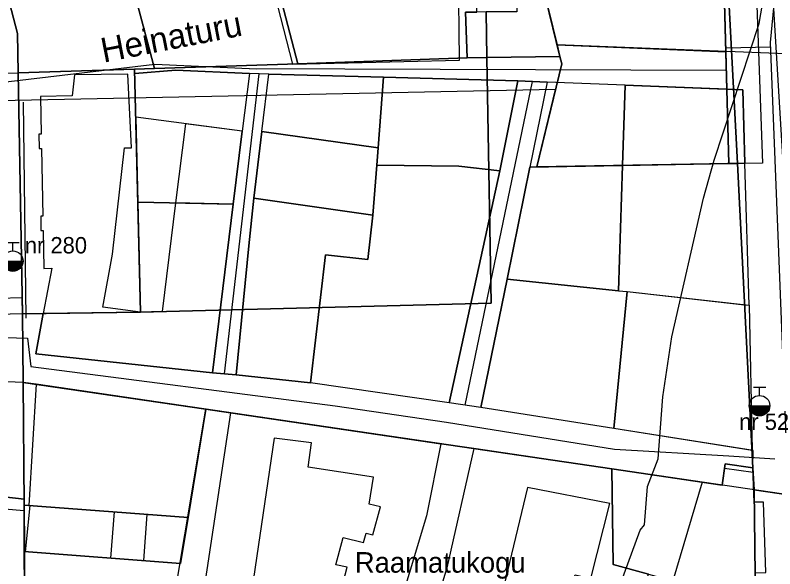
# Model space of a CAD drawing. Extents: x 728832 to 739469, y 6586263 to 6599699.
# Drawn here: x 738581.2 to 738766.3, y 6589820.2 to 6589955.2 of the extents above; entities that cross this region are included whole.
import ezdxf

# ---------------------------------------------------------------- set-up
doc = ezdxf.new("R2010")
doc.units = 0
for name, color, linetype in [('a_kalda_piiranguv', 7, 'Continuous'), ('a_LK_III_kodukakk', 7, 'Continuous'), ('a_piir', 7, 'Continuous'), ('dp_hoonestus', 7, 'Continuous'), ('PIIR', 7, 'Continuous'), ('plan_ala', 7, 'Continuous'), ('v_dp_kaldapromenaad', 7, 'Continuous'), ('v_dp_kehtiv', 7, 'Continuous'), ('v_dp_kehtiv_tekst', 7, 'Continuous'), ('v_dp_tanav_tekst', 7, 'Continuous'), ('v_dp_transp_kergliiklejate_tanav', 7, 'Continuous'), ('v_leppem_katastripiir', 7, 'Continuous'), ('v_olol_hüdrant', 7, 'Continuous'), ('v_olol_katastri_nimi', 7, 'Continuous'), ('v_olol_transp_jjt', 7, 'Continuous'), ('VKAEV', 7, 'Continuous')]:
    doc.layers.add(name, color=color, linetype=linetype)

# ---------------------------------------------------------------- blocks, each defined once
blk = doc.blocks.new('THYDRM_3')
at = {"layer": 'VKAEV'}
for p, q in [((-0.6, 1.8), (0.6, 1.8)), ((0, 1), (0, 1.8)), ((-1, 0), (1, 0))]:
    blk.add_line(p, q, dxfattribs=at)
blk.add_circle((0, 0), 1, dxfattribs=at)
for radius in [0.95, 0.9, 0.85, 0.8, 0.75, 0.7, 0.65, 0.6, 0.55, 0.5, 0.45, 0.4, 0.35, 0.3, 0.25, 0.2, 0.15, 0.1]:
    blk.add_arc((0, 0), radius, 180, 0, dxfattribs=at)

msp = doc.modelspace()

# ---------------------------------------------------------------- linework, layer by layer
at = {"layer": 'a_kalda_piiranguv'}
msp.add_lwpolyline([(738695.61, 6589728.48), (738706.15, 6589759.08), (738722.64, 6589798.76), (738722.69, 6589800.12), (738733.47, 6589829.62), (738734.51, 6589830.94), (738735.22, 6589840.26), (738737.86, 6589847.06), (738738.99, 6589862.11), (738741.2, 6589876.8), (738748.87, 6589910.57), (738751.45, 6589919.82), (738762.48, 6589953.16), (738771.98, 6590008.5), (738779.42, 6590032.77), (738792.73, 6590054.38), (738794.61, 6590056.71), (738798, 6590073.89), (738805.74, 6590098.09)], dxfattribs=at)
at = {"layer": 'a_LK_III_kodukakk'}
msp.add_lwpolyline([(738774.8, 6589988.29), (738764.14, 6589986.28), (738769.19, 6589903.2), (738776.34, 6589779.97), (738793.46, 6589779), (738813.32, 6589799.46), (738821.04, 6589844.98), (738829.66, 6589892.22), (738832, 6589940.61), (738821.77, 6589948.75), (738824.98, 6589976.65)], close=True, dxfattribs=at)
at = {"layer": 'a_piir'}
for points in [[(738716.96, 6590090.08), (738738.99, 6590049.61), (738748.53, 6590037.67), (738752.27, 6590014.17), (738752.88, 6590000.39), (738757.06, 6589920.61), (738757.14, 6589919.04), (738760.94, 6589844.8), (738761.22, 6589839.49), (738773.4, 6589837.7), (738772.93, 6589857.45), (738768.72, 6589952.16), (738772.03, 6590000.09), (738764.49, 6590055.06), (738742.13, 6590093.07)], [(738746.35, 6589684.41), (738770.95, 6589773.79), (738773.02, 6589782.57), (738774.3, 6589799.69), (738773.4, 6589837.7), (738761.22, 6589839.49), (738761.57, 6589811.73), (738761.83, 6589791.03), (738753.47, 6589756.53), (738744.47, 6589720.57)]]:
    msp.add_lwpolyline(points, dxfattribs=at)
for points in [[(738689.52, 6590022.24), (738633.27, 6590007.58), (738650.05, 6589943.32), (738691.26, 6589944.8), (738690.88, 6589955.96), (738693.65, 6589955.95), (738693.65, 6589965.82), (738703.46, 6589965.87), (738703.41, 6589956.03), (738695.91, 6589955.97), (738696.09, 6589944.86), (738713.89, 6589945.13), (738703.51, 6589987.79), (738698.18, 6589986.41)], [(738615.11, 6589942.17), (738650.05, 6589943.32), (738633.27, 6590007.58), (738600.07, 6589998.83)], [(738752.88, 6590000.39), (738703.51, 6589987.79), (738713.89, 6589945.13), (738714.33, 6589943.33), (738708.27, 6589918.18), (738755.04, 6589919)], [(738757.06, 6589920.61), (738752.88, 6590000.39), (738755.04, 6589919), (738757.14, 6589919.04)], [(738615.11, 6589942.17), (738600.07, 6589998.83), (738571.13, 6589991.27), (738581.73, 6589950.74), (738581.9, 6589941.15), (738610.26, 6589942.03)], [(738571.13, 6589991.27), (738553.84, 6589986.61), (738562.2, 6589955.79), (738564.38, 6589947.59), (738565.01, 6589911.26), (738565.45, 6589885.78), (738577.13, 6589865.85), (738573.7, 6589835.23), (738572.34, 6589823.37), (738572.85, 6589780.14), (738565.96, 6589779.81), (738566.36, 6589741.08), (738583.93, 6589742.58), (738583.56, 6589797.78), (738583.38, 6589824.42), (738583.34, 6589835.74), (738583.11, 6589865.67), (738582.94, 6589882.38), (738581.9, 6589941.15), (738581.73, 6589950.74)], [(738696.09, 6589944.86), (738695.91, 6589955.97), (738693.65, 6589955.95), (738690.88, 6589955.96), (738691.26, 6589944.8)], [(738696.09, 6589944.86), (738697.14, 6589884.98), (738611.71, 6589882.8), (738582.94, 6589882.38), (738583.11, 6589865.67), (738627.65, 6589859.12), (738726.53, 6589844.6), (738753.42, 6589840.65), (738754.18, 6589845.8), (738760.94, 6589844.8), (738757.14, 6589919.04), (738755.04, 6589919), (738708.27, 6589918.18), (738714.33, 6589943.33), (738713.89, 6589945.13)], [(738650.05, 6589943.32), (738615.11, 6589942.17), (738610.26, 6589942.03), (738611.71, 6589882.8), (738697.14, 6589884.98), (738696.09, 6589944.86), (738691.26, 6589944.8)], [(738581.9, 6589941.15), (738582.94, 6589882.38), (738611.71, 6589882.8), (738610.26, 6589942.03)], [(738627.65, 6589859.12), (738583.11, 6589865.67), (738583.34, 6589835.74), (738623.29, 6589832.73)], [(738623.29, 6589832.73), (738621.44, 6589821.55), (738583.38, 6589824.42), (738583.56, 6589797.78), (738610.5, 6589797.85), (738634.41, 6589797.92), (738645.6, 6589795.94), (738680.72, 6589789.71), (738724.38, 6589781.99), (738735.47, 6589818.89), (738726.85, 6589821.26), (738726.53, 6589844.6), (738627.65, 6589859.12)], [(738726.53, 6589844.6), (738726.85, 6589821.26), (738735.47, 6589818.89), (738761.57, 6589811.73), (738761.22, 6589839.49), (738760.94, 6589844.8), (738754.18, 6589845.8), (738753.42, 6589840.65)], [(738583.38, 6589824.42), (738621.44, 6589821.55), (738623.29, 6589832.73), (738583.34, 6589835.74)]]:
    msp.add_lwpolyline(points, close=True, dxfattribs=at)
at = {"layer": 'dp_hoonestus'}
msp.add_line((738607.77, 6589922.88), (738609.51, 6589922.85), dxfattribs=at)
for points in [[(738609.51, 6589922.85), (738608.58, 6589940.82), (738595.65, 6589940.61), (738595.08, 6589935.52), (738587.34, 6589935.36), (738587.51, 6589926.18), (738586.91, 6589926.17), (738586.97, 6589922.7), (738587.58, 6589922.71), (738587.9, 6589906.2), (738587.38, 6589906.19), (738587.44, 6589902.71), (738587.97, 6589902.72), (738588.15, 6589893.45), (738590.07, 6589893.5), (738588.02, 6589882.45), (738611.71, 6589882.8), (738602.54, 6589883.97), (738604.89, 6589896.91), (738607.77, 6589922.88)], [(738629.28, 6589868.02), (738634.32, 6589909.08), (738636.51, 6589926.89)]]:
    msp.add_lwpolyline(points, dxfattribs=at)
for points in [[(738638.24, 6589940.95), (738636.51, 6589926.89), (738610.55, 6589930.29), (738610.29, 6589940.96), (738620.34, 6589941.8), (738638.24, 6589940.95)], [(738641.25, 6589926.82), (738642.96, 6589940.78), (738670.91, 6589940.04), (738669.59, 6589922.84), (738641.25, 6589926.82)], [(738669.27, 6589918.64), (738669.59, 6589922.84), (738670.91, 6589940.04), (738703.67, 6589939.18), (738699.26, 6589917.24), (738689.3, 6589918.41), (738669.27, 6589918.64)], [(738710.82, 6589938.87), (738706.6, 6589918.15), (738729.15, 6589918.55), (738729.77, 6589938.09), (738710.82, 6589938.87)], [(738729.15, 6589918.55), (738729.77, 6589938.09), (738758.48, 6589936.98), (738758.99, 6589919.07), (738755.04, 6589919), (738729.15, 6589918.55)], [(738622.63, 6589928.71), (738620.26, 6589909.4), (738634.32, 6589909.08), (738636.51, 6589926.89), (738622.63, 6589928.71)], [(738639.28, 6589910.55), (738641.25, 6589926.82), (738669.59, 6589922.84), (738669.27, 6589918.64), (738668.33, 6589906.41), (738639.28, 6589910.55)], [(738653.16, 6589865.56), (738656.76, 6589896.8), (738667.09, 6589895.61), (738668.33, 6589906.41), (738669.27, 6589918.64), (738689.3, 6589918.41), (738699.26, 6589917.24), (738686.91, 6589860.69), (738653.16, 6589865.56)], [(738706.6, 6589918.15), (738729.15, 6589918.55), (738728.17, 6589888.01), (738701.03, 6589890.82), (738706.6, 6589918.15)], [(738729.15, 6589918.55), (738728.17, 6589888.01), (738730.27, 6589887.79), (738759.98, 6589884.48), (738758.99, 6589919.07), (738729.15, 6589918.55)], [(738620.26, 6589909.4), (738617.01, 6589882.94), (738611.71, 6589882.8), (738588.02, 6589882.45), (738586.18, 6589872.62), (738615.36, 6589869.51), (738629.28, 6589868.02), (738634.32, 6589909.08), (738620.26, 6589909.4)], [(738635, 6589867.5), (738638.13, 6589898.93), (738639.28, 6589910.55), (738668.33, 6589906.41), (738667.09, 6589895.61), (738656.76, 6589896.8), (738653.16, 6589865.56), (738635, 6589867.5)], [(738694.66, 6589859.54), (738701.03, 6589890.82), (738728.17, 6589888.01), (738730.27, 6589887.79), (738727.07, 6589854.42), (738694.66, 6589859.54)], [(738730.27, 6589887.79), (738759.98, 6589884.48), (738760.72, 6589849.1), (738727.07, 6589854.42), (738730.27, 6589887.79)]]:
    msp.add_lwpolyline(points, close=True, dxfattribs=at)
at = {"layer": 'PIIR'}
for points in [[(738638.81, 6589815.08), (738640.53, 6589814.8), (738657.11, 6589810.8), (738657.17, 6589811.05), (738663.17, 6589809.58), (738664.84, 6589815.82), (738661.09, 6589816.92), (738662.08, 6589820.59), (738659.31, 6589821.21), (738661.1, 6589827.82), (738666.07, 6589826.65), (738666.65, 6589828.92), (738668.33, 6589828.52), (738670.17, 6589835.36), (738667.45, 6589835.99), (738668.47, 6589842.54), (738652.59, 6589845), (738653.37, 6589850.95), (738644.27, 6589852.09)], [(738741.43, 6589817.25), (738761.57, 6589811.73), (738761.48, 6589819.2), (738764.07, 6589819.32), (738763.48, 6589836.46), (738761.26, 6589836.45), (738761.22, 6589839.49), (738761, 6589843.69), (738754.02, 6589844.71), (738753.42, 6589840.65), (738748.6, 6589841.36)], [(738696.35, 6589799.74), (738708.31, 6589795.99), (738710.1, 6589802.4), (738718.62, 6589799.79), (738721.96, 6589811.57), (738716.18, 6589813.25), (738717.59, 6589818.79), (738721.47, 6589817.83), (738726.05, 6589836.16), (738706, 6589840.01)], [(738605.27, 6589834.09), (738604.43, 6589822.83), (738583.7, 6589824.4), (738584.85, 6589835.63)], [(738613.23, 6589833.49), (738612.4, 6589822.23), (738621.44, 6589821.55), (738623.29, 6589832.73)]]:
    msp.add_lwpolyline(points, close=True, dxfattribs=at)
at = {"layer": 'plan_ala'}
msp.add_lwpolyline([(738773.4, 6589837.7), (738586.3, 6589865.2), (738586.3, 6589865.2), (738583.11, 6589865.67), (738577.13, 6589865.85), (738565.7, 6589866.14), (738565.45, 6589885.77), (738564.49, 6589941.05), (738581.9, 6589941.15), (738615.11, 6589942.17), (738650.05, 6589943.32), (738691.27, 6589944.8), (738696.09, 6589944.85), (738713.89, 6589945.13), (738703.51, 6589987.79), (738786.92, 6590008.4), (738768.72, 6589952.16)], close=True, dxfattribs=at)
at = {"layer": 'v_dp_kaldapromenaad'}
for p, q in [((738632.14, 6589867.76), (738640.6, 6589940.86)), ((738754.44, 6589941.71), (738638.3, 6589942.12)), ((738690.79, 6589860.12), (738707.24, 6589939.02))]:
    msp.add_line(p, q, dxfattribs=at)
at = {"layer": 'v_dp_kehtiv'}
for points in [[(738572.16, 6589949.69), (738560.05, 6589994.65), (738754.16, 6590045.25), (738754.16, 6590045.25), (738759.38, 6590027.73), (738763.29, 6589919.13), (738757.14, 6589919.04), (738708.27, 6589918.18), (738712.82, 6589937.07), (738573.1, 6589934.21)], [(738560.05, 6589994.65), (738754.16, 6590045.25), (738754.16, 6590045.25), (738759.38, 6590027.73), (738763.29, 6589919.13), (738757.14, 6589919.04), (738708.27, 6589918.18), (738712.82, 6589937.07), (738573.1, 6589934.21), (738572.16, 6589949.69)], [(738689.18, 6589965.94), (738689.18, 6589965.94), (738708.83, 6589965.94), (738703.51, 6589987.79), (738753.01, 6590000.42), (738754.21, 6590000.8), (738753.82, 6590014.6), (738749.4, 6590039.21), (738749.4, 6590039.21), (738631.94, 6590008.72), (738631.94, 6590008.72), (738648.75, 6589943.28), (738648.75, 6589943.28), (738648.75, 6589943.28), (738689.41, 6589944.25), (738689.41, 6589944.25)], [(738689.18, 6589965.94), (738689.18, 6589965.94), (738708.83, 6589965.94), (738703.51, 6589987.79), (738753.01, 6590000.42), (738754.21, 6590000.8), (738753.82, 6590014.6), (738749.4, 6590039.21), (738749.4, 6590039.21), (738631.94, 6590008.72), (738631.94, 6590008.72), (738648.75, 6589943.28), (738648.75, 6589943.28), (738648.75, 6589943.28), (738689.41, 6589944.25), (738689.41, 6589944.25)], [(738696.09, 6589944.85), (738697.14, 6589884.98), (738611.71, 6589882.8), (738582.94, 6589882.38), (738570.92, 6589882.05), (738572.64, 6589797.79), (738583.56, 6589797.78), (738610.5, 6589797.85), (738634.41, 6589797.92), (738645.6, 6589795.94), (738724.38, 6589781.99), (738735.47, 6589818.89), (738761.57, 6589811.73), (738774.1, 6589808.27), (738773.4, 6589837.7), (738768.98, 6589945.74), (738713.21, 6589947.93), (738713.89, 6589945.13)], [(738696.09, 6589944.85), (738697.14, 6589884.98), (738611.71, 6589882.8), (738582.94, 6589882.38), (738570.92, 6589882.05), (738572.64, 6589797.79), (738583.56, 6589797.78), (738610.5, 6589797.85), (738634.41, 6589797.92), (738645.6, 6589795.94), (738724.38, 6589781.99), (738735.47, 6589818.89), (738761.57, 6589811.73), (738774.1, 6589808.27), (738773.4, 6589837.7), (738768.98, 6589945.74), (738713.21, 6589947.93), (738713.89, 6589945.13)], [(738583.69, 6589778.96), (738583.56, 6589797.78), (738583.33, 6589837.2), (738518.88, 6589844.63), (738518.26, 6589795.24), (738518.24, 6589794.66), (738518.47, 6589777.9), (738518.47, 6589777.9), (738583.69, 6589778.96), (738583.69, 6589778.96), (738583.69, 6589778.96)], [(738518.88, 6589844.63), (738518.88, 6589844.63), (738518.88, 6589844.63), (738518.88, 6589844.63), (738583.33, 6589837.2), (738583.33, 6589837.2), (738583.56, 6589797.78), (738583.69, 6589778.96), (738583.69, 6589778.96), (738583.69, 6589778.96), (738518.49, 6589777.9), (738518.47, 6589777.9), (738518.24, 6589794.66), (738518.26, 6589795.24)]]:
    msp.add_lwpolyline(points, close=True, dxfattribs=at)
for points in [[(738573.7, 6589835.23), (738583.34, 6589834.45), (738583.34, 6589835.74), (738583.11, 6589865.67), (738582.94, 6589882.36), (738582.87, 6589886.28), (738565.45, 6589885.77)], [(738573.7, 6589835.23), (738583.34, 6589834.45), (738583.34, 6589835.74), (738583.11, 6589865.67), (738582.94, 6589882.38), (738582.87, 6589886.28), (738565.45, 6589885.77)]]:
    msp.add_lwpolyline(points, dxfattribs=at)
at = {"layer": 'v_dp_transp_kergliiklejate_tanav'}
for p, q in [((738754.29, 6589947.22), (738765.2, 6589947.47)), ((738583.87, 6589881.32), (738583.17, 6589934.01))]:
    msp.add_line(p, q, dxfattribs=at)
for points in [[(738566.56, 6589937.49), (738615.22, 6589943.27), (738639.96, 6589942.08)], [(738568.16, 6589876.93), (738584.15, 6589876.47), (738585, 6589869.54), (738659.13, 6589859.93), (738686.28, 6589855.99), (738727.22, 6589849.37), (738755.03, 6589847.73), (738766.25, 6589847.05)]]:
    msp.add_lwpolyline(points, dxfattribs=at)
at = {"layer": 'v_leppem_katastripiir'}
for p, q in [((738586.3, 6589865.2), (738627.65, 6589859.12)), ((738633.66, 6589858.24), (738684.92, 6589850.71)), ((738748.6, 6589841.36), (738741.43, 6589817.25)), ((738584.46, 6589835.66), (738623.29, 6589832.73)), ((738583.38, 6589824.42), (738621.44, 6589821.55))]:
    msp.add_line(p, q, dxfattribs=at)
for points in [[(738584.46, 6589835.66), (738583.34, 6589835.74), (738583.11, 6589865.67), (738586.3, 6589865.2)], [(738617.39, 6589797.87), (738627.65, 6589859.12), (738633.66, 6589858.24), (738624.54, 6589797.89)]]:
    msp.add_lwpolyline(points, close=True, dxfattribs=at)
for points in [[(738624.54, 6589797.89), (738634.41, 6589797.92), (738645.6, 6589795.94), (738668.95, 6589791.8), (738680.72, 6589789.71), (738724.38, 6589781.99), (738735.47, 6589818.89), (738761.57, 6589811.73), (738761.48, 6589819.2), (738764.07, 6589819.32), (738763.48, 6589836.46), (738761.26, 6589836.45), (738760.94, 6589844.8), (738754.18, 6589845.8), (738753.42, 6589840.65), (738692.91, 6589849.54), (738684.92, 6589850.71)], [(738684.92, 6589850.71), (738681.41, 6589833.16), (738668.95, 6589791.8)], [(738692.91, 6589849.54), (738686.35, 6589820.43), (738677.23, 6589790.33)], [(738583.34, 6589835.74), (738583.56, 6589797.78), (738610.5, 6589797.85), (738617.39, 6589797.87)]]:
    msp.add_lwpolyline(points, dxfattribs=at)
at = {"layer": 'v_olol_katastri_nimi'}
for points in [[(738703.51, 6589987.79), (738713.21, 6589947.93), (738754.32, 6589946.29), (738752.88, 6590000.39)], [(738753.45, 6589979.08), (738754.32, 6589946.29), (738713.21, 6589947.93), (738708.29, 6589968.15)], [(738754.32, 6589946.29), (738754.56, 6589937.13), (738729.77, 6589938.09), (738710.82, 6589938.87), (738703.67, 6589939.18), (738670.91, 6589940.04), (738642.96, 6589940.78), (738638.24, 6589940.95), (738620.34, 6589941.8), (738610.29, 6589940.96), (738610.26, 6589942.02), (738615.11, 6589942.17), (738650.05, 6589943.32), (738691.26, 6589944.8), (738696.09, 6589944.86), (738713.89, 6589945.13), (738713.21, 6589947.93)], [(738754.32, 6589946.29), (738754.56, 6589937.13), (738729.77, 6589938.09), (738710.82, 6589938.87), (738703.67, 6589939.18), (738670.91, 6589940.04), (738642.96, 6589940.78), (738638.24, 6589940.95), (738620.34, 6589941.8), (738610.29, 6589940.96), (738610.26, 6589942.02), (738615.11, 6589942.17), (738650.05, 6589943.32), (738691.26, 6589944.8), (738696.09, 6589944.86), (738713.89, 6589945.13), (738713.21, 6589947.93)], [(738610.55, 6589930.29), (738610.29, 6589940.96), (738620.34, 6589941.8), (738638.24, 6589940.95), (738636.51, 6589926.89)], [(738642.96, 6589940.78), (738638.24, 6589940.95), (738636.51, 6589926.89), (738634.32, 6589909.08), (738629.28, 6589868.02), (738635, 6589867.5), (738638.13, 6589898.93), (738639.28, 6589910.55), (738641.25, 6589926.82)], [(738641.25, 6589926.82), (738642.96, 6589940.78), (738670.91, 6589940.04), (738669.59, 6589922.84)], [(738669.27, 6589918.64), (738669.59, 6589922.84), (738670.91, 6589940.04), (738703.67, 6589939.18), (738699.26, 6589917.24), (738689.3, 6589918.41)], [(738703.67, 6589939.18), (738710.82, 6589938.87), (738706.6, 6589918.15), (738701.03, 6589890.82), (738694.66, 6589859.54), (738686.91, 6589860.69), (738699.26, 6589917.24)], [(738703.67, 6589939.18), (738710.82, 6589938.87), (738706.6, 6589918.15), (738701.03, 6589890.82), (738694.66, 6589859.54), (738686.91, 6589860.69), (738699.26, 6589917.24)], [(738729.77, 6589938.09), (738710.82, 6589938.87), (738706.6, 6589918.15), (738729.15, 6589918.55)], [(738729.77, 6589938.09), (738729.15, 6589918.55), (738755.04, 6589919), (738758.99, 6589919.07), (738758.48, 6589936.98), (738754.56, 6589937.13)], [(738611.05, 6589909.62), (738634.32, 6589909.08), (738636.51, 6589926.89), (738636.51, 6589926.89), (738610.55, 6589930.29)], [(738641.25, 6589926.82), (738639.28, 6589910.55), (738668.33, 6589906.41), (738669.27, 6589918.64), (738669.59, 6589922.84)], [(738669.27, 6589918.64), (738689.3, 6589918.41), (738699.26, 6589917.24), (738699.26, 6589917.24), (738686.91, 6589860.69), (738653.16, 6589865.56), (738656.76, 6589896.8), (738667.09, 6589895.61), (738668.33, 6589906.41)], [(738729.15, 6589918.55), (738706.6, 6589918.15), (738701.03, 6589890.82), (738728.17, 6589888.01)], [(738729.15, 6589918.55), (738728.17, 6589888.01), (738730.27, 6589887.79), (738758.9, 6589884.6), (738759.98, 6589884.48), (738758.99, 6589919.07), (738755.04, 6589919)], [(738586.18, 6589872.62), (738629.28, 6589868.02), (738634.32, 6589909.08), (738611.05, 6589909.62), (738611.71, 6589882.8), (738588.02, 6589882.45)], [(738635, 6589867.5), (738653.16, 6589865.56), (738656.76, 6589896.8), (738667.09, 6589895.61), (738668.33, 6589906.41), (738639.28, 6589910.55), (738638.13, 6589898.93)], [(738701.03, 6589890.82), (738728.17, 6589888.01), (738730.27, 6589887.79), (738727.07, 6589854.42), (738694.66, 6589859.54)], [(738730.27, 6589887.79), (738759.98, 6589884.48), (738760.72, 6589849.1), (738727.07, 6589854.42)], [(738588.02, 6589882.45), (738582.94, 6589882.38), (738583.11, 6589865.67), (738585.5, 6589865.32), (738627.65, 6589859.12), (738692.91, 6589849.54), (738726.53, 6589844.59), (738748.6, 6589841.36), (738753.42, 6589840.65), (738754.18, 6589845.8), (738760.94, 6589844.8), (738760.72, 6589849.1), (738727.07, 6589854.42), (738694.66, 6589859.54), (738686.91, 6589860.69), (738653.16, 6589865.56), (738635, 6589867.5), (738629.28, 6589868.02), (738586.18, 6589872.62)], [(738588.02, 6589882.45), (738582.94, 6589882.38), (738583.11, 6589865.67), (738585.5, 6589865.32), (738627.65, 6589859.12), (738692.91, 6589849.54), (738726.53, 6589844.59), (738748.6, 6589841.36), (738753.42, 6589840.65), (738754.18, 6589845.8), (738760.94, 6589844.8), (738760.72, 6589849.1), (738727.07, 6589854.42), (738694.66, 6589859.54), (738686.91, 6589860.69), (738653.16, 6589865.56), (738635, 6589867.5), (738629.28, 6589868.02), (738586.18, 6589872.62)], [(738588.02, 6589882.45), (738582.94, 6589882.38), (738583.11, 6589865.67), (738585.5, 6589865.32), (738627.65, 6589859.12), (738692.91, 6589849.54), (738726.53, 6589844.59), (738748.6, 6589841.36), (738753.42, 6589840.65), (738754.18, 6589845.8), (738760.94, 6589844.8), (738760.99, 6589849.05), (738727.07, 6589854.42), (738694.66, 6589859.54), (738686.91, 6589860.69), (738653.16, 6589865.56), (738635, 6589867.5), (738629.28, 6589868.02), (738586.18, 6589872.62)]]:
    msp.add_lwpolyline(points, close=True, dxfattribs=at)
at = {"layer": 'v_olol_transp_jjt'}
msp.add_lwpolyline([(738739.83, 6590092.1), (738762.58, 6590052.49), (738765.8, 6590018.73), (738770.03, 6589999.23), (738765.16, 6589948.51), (738770.96, 6589801.22), (738770.96, 6589784.65), (738744.05, 6589687.94), (738732.19, 6589650.65), (738704.24, 6589618.95), (738677.81, 6589602.35), (738554.06, 6589547.05), (738495.74, 6589520.07)], dxfattribs=at)

# ---------------------------------------------------------------- block references
at = {"layer": 'v_olol_hüdrant', "xscale": 2.5, "yscale": 2.5}
for p in [(738580.6, 6589895.23), (738762.55, 6589859.98)]:
    msp.add_blockref('THYDRM_3', p, dxfattribs=at)

# ---------------------------------------------------------------- texts
at = {"layer": 'v_dp_kehtiv_tekst'}
msp.add_text('Raamatukogu', height=5, dxfattribs=at).set_placement((738663.92, 6589819.28))
at = {"layer": 'v_dp_tanav_tekst'}
msp.add_text('Heinaturu', height=6, rotation=11.0716, dxfattribs=at).set_placement((738602.69, 6589943.59))
at = {"layer": 'v_olol_hüdrant'}
for s, p in [('nr 280', (738583.51, 6589897.1)), ('nr 52', (738757.57, 6589854.08))]:
    msp.add_text(s, height=4, dxfattribs=at).set_placement(p)

doc.saveas('drawing.dxf')
